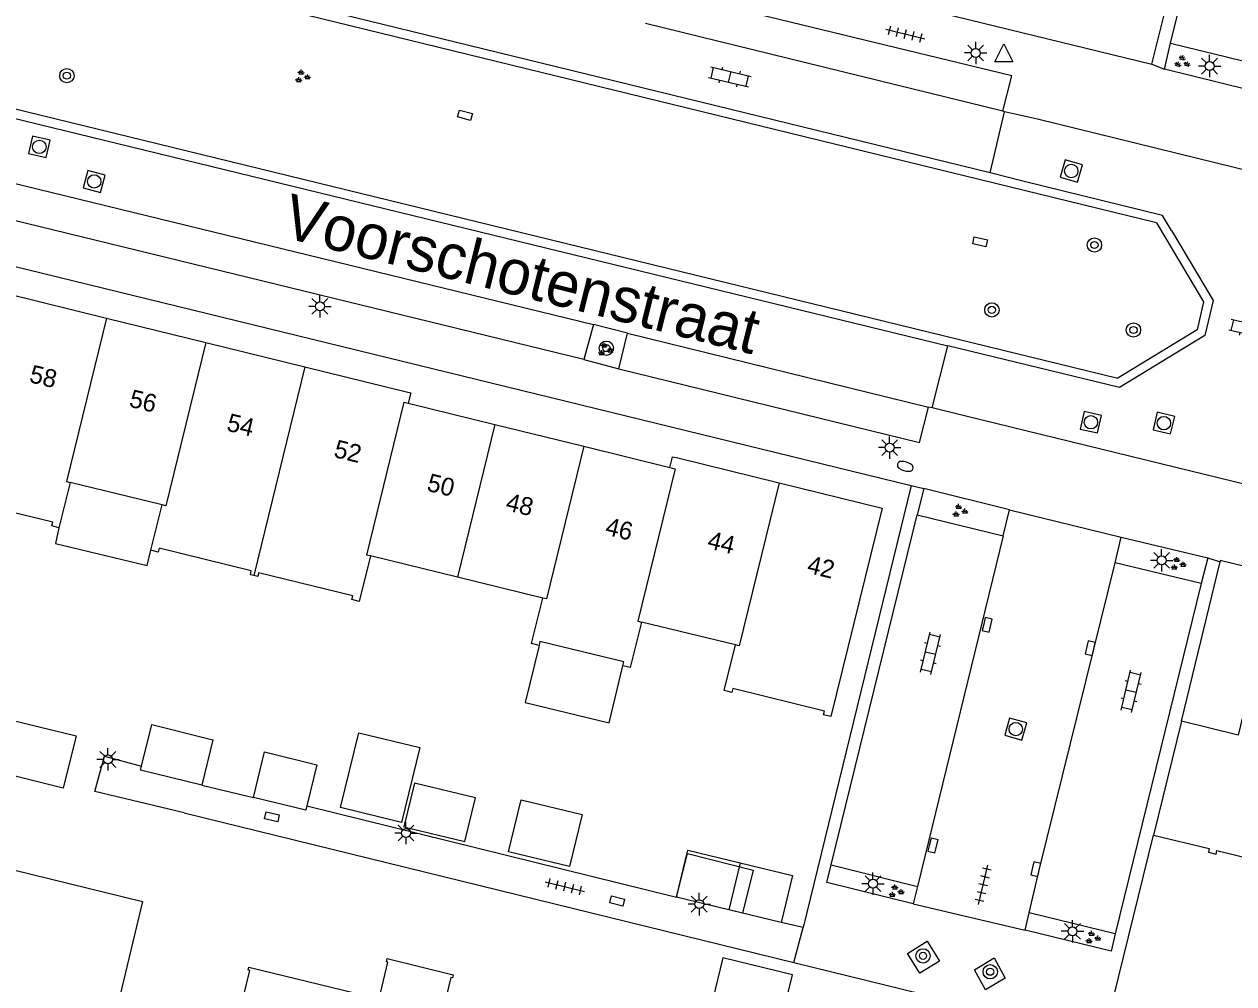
# Model space of a CAD drawing. Extents: x 125000 to 129004, y 397500 to 399008.
# Drawn here: x 126369.4 to 126436.9, y 398219.6 to 398273.2 of the extents above; entities that cross this region are included whole.
import ezdxf

# ---------------------------------------------------------------- set-up
doc = ezdxf.new("R2010")
doc.units = 0
for name, color, linetype in [('gg-afsc-erfafscheiding', 7, 'Continuous'), ('gg-afsc-hekwerk', 7, 'Continuous'), ('gg-afsc-muur', 7, 'Continuous'), ('gg-anno-huisnummerreeks BGT', 7, 'Continuous'), ('gg-anno-openbare ruimte label', 7, 'Continuous'), ('gg-bbg-bijgebouw', 7, 'Continuous'), ('gg-bbg-gedigitaliseerde bijgebouw', 7, 'Continuous'), ('gg-bbg-hoofdgebouw', 7, 'Continuous'), ('gg-bbg-luifel en loopbrug', 7, 'Continuous'), ('gg-bbg-tussenscheiding', 7, 'Continuous'), ('gg-knt-verharding', 7, 'Continuous'), ('gg-knt-verharding nz', 7, 'Continuous'), ('gt-bbg-plantopografie pand', 7, 'Continuous'), ('gt-grn-weggrens', 7, 'Continuous'), ('gt-symb-boom', 7, 'Continuous'), ('gt-symb-brandkraan', 7, 'Continuous'), ('gt-symb-groenvak', 7, 'Continuous'), ('gt-symb-klinker verharding', 7, 'Continuous'), ('gt-symb-kolk', 7, 'Continuous'), ('gt-symb-kolk center center', 7, 'Continuous'), ('gt-symb-lichtmast', 7, 'Continuous'), ('gt-symb-rioolschacht', 7, 'Continuous'), ('gt-symb-tegel verharding', 7, 'Continuous'), ('gt-symb-waterafsluiter', 7, 'Continuous')]:
    doc.layers.add(name, color=color, linetype=linetype)

# ---------------------------------------------------------------- blocks, each defined once
blk = doc.blocks.new('gt0-LMAST')
at = {"layer": 'gt-symb-lichtmast'}
for p, q in [((-0.182, 0.173), (-0.447, 0.438)), ((-0.005, 0.246), (-0.005, 0.621)), ((0.172, 0.173), (0.437, 0.438)), ((-0.255, -0.004), (-0.63, -0.004)), ((-0.182, -0.181), (-0.447, -0.446)), ((-0.005, -0.254), (-0.005, -0.629)), ((0.437, -0.446), (0.172, -0.181)), ((0.245, -0.004), (0.62, -0.004))]:
    blk.add_line(p, q, dxfattribs=at)
blk.add_circle((-0.005, -0.004), 0.25, dxfattribs=at)
blk = doc.blocks.new('gt0-GRVAK')
at = {"layer": 'gt-symb-groenvak'}
for p, q in [((-0.11, 0.189), (-0.228, 0.24)), ((-0.182, 0.153), (0.088, 0.153)), ((-0.091, 0.211), (-0.156, 0.322)), ((-0.047, 0.214), (-0.047, 0.393)), ((-0.004, 0.211), (0.061, 0.322)), ((0.015, 0.189), (0.133, 0.24)), ((0.262, -0.052), (0.197, 0.059)), ((0.305, -0.049), (0.305, 0.13)), ((0.349, -0.052), (0.414, 0.059)), ((-0.245, -0.228), (-0.363, -0.177)), ((-0.318, -0.264), (-0.047, -0.264)), ((-0.226, -0.206), (-0.291, -0.095)), ((-0.183, -0.203), (-0.183, -0.024)), ((-0.139, -0.206), (-0.074, -0.095)), ((-0.12, -0.228), (-0.002, -0.177)), ((0.243, -0.074), (0.125, -0.023)), ((0.17, -0.11), (0.441, -0.11)), ((0.368, -0.074), (0.486, -0.023))]:
    blk.add_line(p, q, dxfattribs=at)
blk = doc.blocks.new('gt0-WAFSL')
at = {"layer": 'gt-symb-waterafsluiter'}
for p, q in [((-0.5, -0.333), (0, 0.667)), ((0, 0.667), (0.5, -0.333)), ((0.5, -0.333), (-0.5, -0.333))]:
    blk.add_line(p, q, dxfattribs=at)
blk = doc.blocks.new('gt0-RS')
at = {"layer": 'gt-symb-rioolschacht'}
blk.add_lwpolyline([(-0.5, -0.5), (0.5, -0.5), (0.5, 0.5), (-0.5, 0.5)], close=True, dxfattribs=at)
blk.add_circle((0, 0), 0.375, dxfattribs=at)
blk = doc.blocks.new('gt0-BOOM')
at = {"layer": 'gt-symb-boom'}
for radius in [0.4, 0.2]:
    blk.add_circle((0, 0), radius, dxfattribs=at)
blk = doc.blocks.new('gt0-KL1')
at = {"layer": 'gt-symb-klinker verharding'}
for p, q in [((-1.15, 0.3), (1.15, 0.3)), ((-1, -0.3), (-1, 0.3)), ((-0.5, 0.3), (-0.5, 0.45)), ((0, -0.3), (0, 0.3)), ((0.5, 0.3), (0.5, 0.45)), ((1, -0.3), (1, 0.3)), ((-1.15, -0.3), (1.15, -0.3)), ((-0.5, -0.45), (-0.5, -0.3)), ((0.5, -0.45), (0.5, -0.3))]:
    blk.add_line(p, q, dxfattribs=at)
blk = doc.blocks.new('gt0-KOLKCC')
at = {"layer": 'gt-symb-kolk center center'}
blk.add_lwpolyline([(-0.375, 0.2), (0.375, 0.2), (0.375, -0.2), (-0.375, -0.2)], close=True, dxfattribs=at)
blk = doc.blocks.new('gt0-KOLK')
at = {"layer": 'gt-symb-kolk'}
blk.add_lwpolyline([(0, 0), (0.375, 0), (0.375, 0.4), (-0.375, 0.4), (-0.375, 0), (0, 0)], dxfattribs=at)
blk = doc.blocks.new('gt0-TEG1')
at = {"layer": 'gt-symb-tegel verharding'}
for p, q in [((-1.125, 0), (1.125, 0)), ((-0.9, -0.25), (-0.9, 0.25)), ((-0.45, -0.25), (-0.45, 0.25)), ((0, -0.25), (0, 0.25)), ((0.45, -0.25), (0.45, 0.25)), ((0.9, -0.25), (0.9, 0.25))]:
    blk.add_line(p, q, dxfattribs=at)
blk = doc.blocks.new('gt0-BR')
at = {"layer": 'gt-symb-brandkraan'}
for centre, radius, start, end in [((-0.244, 0), 0.206, 107.56694, 252.43307), ((0.599, -2.664), 3, 106.89205, 107.56694), ((0, -0.691), 0.938, 73.10799, 106.89205), ((-0.599, -2.664), 3, 72.43309, 73.10799), ((0.244, 0), 0.206, 287.56695, 72.43309), ((0.599, 2.664), 3, 252.43307, 253.10797), ((0, 0.691), 0.938, 253.10797, 286.89206), ((-0.599, 2.664), 3, 286.89206, 287.56695)]:
    blk.add_arc(centre, radius, start, end, dxfattribs=at)

msp = doc.modelspace()

# ---------------------------------------------------------------- linework, layer by layer
at = {"layer": 'gg-afsc-erfafscheiding'}
for p, q in [((126379.348, 398230.678), (126382.237, 398229.993)), ((126385.218, 398229.527), (126405.834, 398224.429))]:
    msp.add_line(p, q, dxfattribs=at)
msp.add_lwpolyline([(126373.387, 398230.333), (126373.917, 398232.305), (126375.989, 398231.752)], dxfattribs=at)
at = {"layer": 'gg-afsc-hekwerk'}
for p, q in [((126432.346, 398270.92), (126434.347, 398278.885)), ((126418.934, 398247.413), (126412.894, 398222.733)), ((126434.011, 398234.258), (126436.166, 398243.146)), ((126378.37, 398229.14), (126412.376, 398220.79)), ((126412.894, 398222.733), (126411.668, 398223.028))]:
    msp.add_line(p, q, dxfattribs=at)
msp.add_lwpolyline([(126412.376, 398220.79), (126429.666, 398216.545), (126432.45, 398227.902)], dxfattribs=at)
at = {"layer": 'gg-afsc-muur'}
msp.add_line((126378.37, 398229.14), (126373.387, 398230.333), dxfattribs=at)
at = {"layer": 'gg-bbg-bijgebouw'}
for points in [[(126375.989, 398231.752), (126376.559, 398234.064), (126379.976, 398233.221), (126379.348, 398230.678)], [(126382.237, 398229.993), (126382.86, 398232.541), (126385.778, 398231.828), (126385.218, 398229.527)], [(126379.348, 398230.678), (126375.932, 398231.522), (126375.989, 398231.752)], [(126385.218, 398229.527), (126385.158, 398229.282), (126382.237, 398229.993)]]:
    msp.add_lwpolyline(points, dxfattribs=at)
at = {"layer": 'gg-bbg-gedigitaliseerde bijgebouw'}
for p, q in [((126409.382, 398226.354), (126408.751, 398223.729)), ((126408.751, 398223.729), (126405.834, 398224.429))]:
    msp.add_line(p, q, dxfattribs=at)
for points in [[(126368.747, 398234.32), (126372.34, 398233.437), (126371.624, 398230.524), (126368.031, 398231.407), (126368.747, 398234.32)], [(126391.51, 398232.786), (126390.493, 398228.608), (126387.092, 398229.435), (126388.109, 398233.613), (126391.51, 398232.786)], [(126391.215, 398230.795), (126390.629, 398228.365), (126394.031, 398227.544), (126394.617, 398229.975), (126391.215, 398230.795)], [(126396.462, 398226.958), (126397.165, 398229.875), (126400.567, 398229.054), (126399.864, 398226.138), (126396.462, 398226.958)], [(126405.834, 398224.429), (126406.465, 398227.054), (126409.382, 398226.354)]]:
    msp.add_lwpolyline(points, dxfattribs=at)
at = {"layer": 'gg-bbg-hoofdgebouw'}
for p, q in [((126368.481, 398258.116), (126374.032, 398256.751)), ((126374.032, 398256.751), (126379.57, 398255.389)), ((126379.57, 398255.389), (126385.105, 398254.028)), ((126385.105, 398254.028), (126390.78, 398252.633)), ((126390.866, 398252.004), (126395.705, 398250.814)), ((126395.705, 398250.814), (126400.664, 398249.595)), ((126400.664, 398249.595), (126405.471, 398248.413)), ((126405.902, 398248.946), (126411.557, 398247.556)), ((126372.008, 398247.582), (126371.386, 398245.051)), ((126377.136, 398246.321), (126372.008, 398247.582)), ((126411.557, 398247.556), (126417.319, 398246.139)), ((126376.514, 398243.791), (126377.136, 398246.321)), ((126393.619, 398242.288), (126388.759, 398243.474)), ((126398.37, 398241.128), (126393.619, 398242.288)), ((126409.12, 398238.508), (126403.875, 398239.782)), ((126434.011, 398234.258), (126432.45, 398227.902))]:
    msp.add_line(p, q, dxfattribs=at)
for points in [[(126390.78, 398252.633), (126391.007, 398252.577), (126390.866, 398252.004)], [(126405.471, 398248.413), (126405.619, 398249.016), (126405.902, 398248.946)], [(126371.386, 398245.051), (126370.981, 398245.155), (126371.035, 398245.368), (126365.888, 398246.609), (126365.839, 398246.405), (126365.631, 398246.459)], [(126417.319, 398246.139), (126414.45, 398234.511), (126414.041, 398234.606), (126414.091, 398234.82), (126408.971, 398236.078), (126408.918, 398235.864), (126408.71, 398235.914)], [(126382.257, 398242.381), (126382.062, 398242.43), (126382.115, 398242.643), (126376.97, 398243.904), (126376.918, 398243.69), (126376.514, 398243.791)], [(126388.759, 398243.474), (126388.141, 398240.94), (126387.933, 398240.991)], [(126387.933, 398240.991), (126387.724, 398241.042), (126387.776, 398241.256), (126382.523, 398242.542), (126382.471, 398242.328), (126382.257, 398242.381)], [(126398.167, 398238.483), (126397.749, 398238.585), (126398.37, 398241.128)], [(126438.98, 398240.933), (126437.167, 398233.483), (126434.011, 398234.258)], [(126403.875, 398239.782), (126403.26, 398237.247), (126402.845, 398237.345)], [(126402.845, 398237.345), (126402.896, 398237.56), (126398.219, 398238.697), (126398.167, 398238.483)], [(126408.71, 398235.914), (126408.502, 398235.964), (126409.12, 398238.508)], [(126432.45, 398227.902), (126435.56, 398227.143), (126435.512, 398226.937), (126435.935, 398226.833), (126435.985, 398227.041), (126441.133, 398225.781), (126441.081, 398225.574), (126441.296, 398225.52)], [(126363.351, 398223.864), (126368.055, 398222.709), (126368.85, 398225.953), (126376.045, 398224.19), (126373.902, 398215.263), (126370.093, 398216.172), (126369.495, 398213.806), (126368.707, 398213.995), (126368.149, 398211.671), (126360.814, 398213.434)], [(126379.277, 398209.069), (126382.026, 398220.333), (126381.939, 398220.357), (126381.986, 398220.528), (126389.254, 398218.763), (126389.737, 398220.809), (126389.65, 398220.83), (126389.695, 398221.015), (126393.385, 398220.109), (126393.34, 398219.924), (126393.252, 398219.946), (126391.71, 398213.545)]]:
    msp.add_lwpolyline(points, dxfattribs=at)
at = {"layer": 'gg-bbg-luifel en loopbrug'}
msp.add_line((126411.668, 398223.028), (126408.751, 398223.729), dxfattribs=at)
for points in [[(126371.386, 398245.051), (126371.188, 398244.18), (126376.31, 398242.944), (126376.514, 398243.791)], [(126398.167, 398238.483), (126397.399, 398235.295), (126402.078, 398234.166), (126402.845, 398237.345)], [(126409.382, 398226.354), (126412.299, 398225.653), (126411.668, 398223.028)], [(126411.051, 398214.946), (126412.307, 398220.095), (126408.421, 398221.043), (126407.11, 398215.67)]]:
    msp.add_lwpolyline(points, dxfattribs=at)
at = {"layer": 'gg-bbg-tussenscheiding'}
for p, q in [((126385.105, 398254.028), (126382.257, 398242.381)), ((126395.705, 398250.814), (126393.619, 398242.288))]:
    msp.add_line(p, q, dxfattribs=at)
for points in [[(126374.032, 398256.751), (126371.802, 398247.633), (126372.008, 398247.582)], [(126379.57, 398255.389), (126377.34, 398246.271), (126377.136, 398246.321)], [(126388.759, 398243.474), (126388.553, 398243.524), (126390.64, 398252.06), (126390.866, 398252.004)], [(126400.664, 398249.595), (126398.58, 398241.077), (126398.37, 398241.128)], [(126405.471, 398248.413), (126405.755, 398248.343), (126403.673, 398239.831), (126403.875, 398239.782)], [(126411.557, 398247.556), (126409.332, 398238.457), (126409.12, 398238.508)]]:
    msp.add_lwpolyline(points, dxfattribs=at)
at = {"layer": 'gg-knt-verharding'}
for p, q in [((126333.839, 398295.002), (126432.346, 398270.92)), ((126433.403, 398272.088), (126438.669, 398293.39)), ((126328.44, 398278.308), (126430.454, 398253.401)), ((126329.473, 398277.528), (126420.97, 398255.202)), ((126433.053, 398270.635), (126433.403, 398272.088)), ((126433.403, 398272.088), (126438.194, 398270.92)), ((126400.663, 398254.432), (126335.48, 398270.359)), ((126437.802, 398269.467), (126433.053, 398270.635)), ((126327.675, 398269.71), (126418.934, 398247.413)), ((126423.334, 398264.85), (126424.139, 398268.27)), ((126424.139, 398268.27), (126424.036, 398268.3)), ((126425.164, 398264.383), (126423.334, 398264.85)), ((126401.204, 398256.387), (126400.663, 398254.432)), ((126403.108, 398255.911), (126401.204, 398256.387)), ((126402.618, 398253.912), (126403.108, 398255.911)), ((126420.108, 398251.75), (126420.97, 398255.202)), ((126400.663, 398254.432), (126402.618, 398253.912)), ((126420.108, 398251.75), (126419.9, 398251.773)), ((126419.634, 398247.232), (126419.257, 398245.769)), ((126424.409, 398246.056), (126419.634, 398247.232)), ((126424.053, 398244.6), (126424.409, 398246.056)), ((126414.464, 398226.236), (126419.257, 398245.769)), ((126419.257, 398245.769), (126424.053, 398244.6)), ((126424.053, 398244.6), (126419.276, 398225.035)), ((126430.31, 398243.093), (126430.644, 398244.534)), ((126430.644, 398244.534), (126435.486, 398243.363)), ((126435.113, 398241.948), (126430.31, 398243.093)), ((126435.486, 398243.363), (126435.113, 398241.948)), ((126435.113, 398241.948), (126430.316, 398222.383)), ((126414.464, 398226.236), (126419.276, 398225.035)), ((126419.276, 398225.035), (126419.041, 398224.065)), ((126425.282, 398222.589), (126425.508, 398223.559)), ((126430.316, 398222.383), (126425.508, 398223.559))]:
    msp.add_line(p, q, dxfattribs=at)
for points in [[(126432.617, 398262.065), (126336.086, 398285.673), (126329.906, 398287.175)], [(126423.334, 398264.85), (126336.206, 398286.158), (126331.881, 398287.232)], [(126424.036, 398268.3), (126424.546, 398270.278), (126404.573, 398275.128)], [(126453.519, 398261.075), (126425.974, 398267.855), (126424.139, 398268.27)], [(126433.456, 398261.633), (126432.953, 398262.473), (126425.164, 398264.383)], [(126432.617, 398262.065), (126435.244, 398257.654), (126434.875, 398256.095), (126430.454, 398253.401)], [(126433.456, 398261.633), (126435.777, 398257.736), (126435.314, 398255.777), (126430.542, 398252.869), (126420.97, 398255.202)], [(126402.618, 398253.912), (126419.395, 398249.811), (126419.9, 398251.773)], [(126449.701, 398244.529), (126447.843, 398244.953), (126421.979, 398251.27), (126420.108, 398251.75)], [(126425.508, 398223.559), (126426.076, 398225.949), (126429.11, 398238.276), (126430.31, 398243.093)], [(126483.908, 398231.619), (126436.172, 398243.227), (126436.166, 398243.146)], [(126419.041, 398224.065), (126414.226, 398225.258), (126414.464, 398226.236)], [(126430.316, 398222.383), (126430.077, 398221.423), (126425.282, 398222.589)], [(126418.714, 398221.298), (126419.811, 398221.97), (126420.503, 398220.867), (126419.406, 398220.194), (126418.714, 398221.298)], [(126422.457, 398220.385), (126423.549, 398221.046), (126424.166, 398219.917), (126423.074, 398219.256), (126422.457, 398220.385)]]:
    msp.add_lwpolyline(points, dxfattribs=at)
at = {"layer": 'gg-knt-verharding nz'}
for p, q in [((126424.036, 398268.3), (126404.114, 398273.191)), ((126335.947, 398272.314), (126401.204, 398256.387)), ((126403.108, 398255.911), (126419.9, 398251.773))]:
    msp.add_line(p, q, dxfattribs=at)
at = {"layer": 'gt-bbg-plantopografie pand'}
msp.add_lwpolyline([(126405.834, 398224.429), (126406.453, 398226.873), (126410.121, 398225.945), (126409.513, 398223.546), (126405.834, 398224.429)], dxfattribs=at)
at = {"layer": 'gt-grn-weggrens'}
for p, q in [((126432.346, 398270.92), (126433.053, 398270.635)), ((126418.934, 398247.413), (126419.634, 398247.232)), ((126424.409, 398246.056), (126430.644, 398244.534)), ((126435.486, 398243.363), (126436.166, 398243.146)), ((126419.041, 398224.065), (126425.282, 398222.589)), ((126412.376, 398220.79), (126412.894, 398222.733))]:
    msp.add_line(p, q, dxfattribs=at)

# ---------------------------------------------------------------- block references
at = {"layer": 'gt-symb-boom'}
for p in [(126371.825, 398270.279), (126429.152, 398260.83), (126423.429, 398257.208), (126431.331, 398256.086), (126401.924, 398255.07), (126419.588, 398221.16), (126423.336, 398220.273)]:
    msp.add_blockref('gt0-BOOM', p, dxfattribs=at)
at = {"layer": 'gt-symb-brandkraan', "rotation": -16.73216022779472}
msp.add_blockref('gt0-BR', (126418.598, 398248.476), dxfattribs=at)
at = {"layer": 'gt-symb-groenvak', "rotation": -15.7172524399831}
msp.add_blockref('gt0-GRVAK', (126434.032, 398271.031), dxfattribs=at)
at = {"layer": 'gt-symb-groenvak'}
for p in [(126384.946, 398270.224), (126401.848, 398254.986), (126421.623, 398245.987), (126433.795, 398243.025), (126418.064, 398224.754), (126429.041, 398222.166)]:
    msp.add_blockref('gt0-GRVAK', p, dxfattribs=at)
at = {"layer": 'gt-symb-klinker verharding'}
for p, rotation in [((126408.81, 398270.211), -13.174926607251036), ((126437.831, 398256.13), -13.174926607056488), ((126420.004, 398238.044), 76.58892815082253), ((126431.197, 398235.923), 76.58892815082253)]:
    msp.add_blockref('gt0-KL1', p, dxfattribs=dict(at, rotation=rotation))
at = {"layer": 'gt-symb-kolk'}
for p, rotation in [((126422.974, 398239.676), -102.35482691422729), ((126429.11, 398238.276), 76.1722049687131), ((126419.951, 398227.368), -103.82779503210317), ((126426.076, 398225.949), 76.64465903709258)]:
    msp.add_blockref('gt0-KOLK', p, dxfattribs=dict(at, rotation=rotation))
at = {"layer": 'gt-symb-kolk center center'}
for p, rotation in [((126394.034, 398268.073), 165.35262473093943), ((126422.772, 398261.012), 167.3531465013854), ((126383.265, 398228.926), -12.827123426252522), ((126402.531, 398224.218), -14.119602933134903)]:
    msp.add_blockref('gt0-KOLKCC', p, dxfattribs=dict(at, rotation=rotation))
at = {"layer": 'gt-symb-lichtmast'}
for p in [(126422.533, 398271.55), (126435.58, 398270.818), (126385.946, 398257.41), (126417.73, 398249.528), (126432.905, 398243.236), (126374.119, 398232.125), (126390.748, 398228.017), (126416.801, 398225.188), (126407.11, 398224.049), (126427.932, 398222.535)]:
    msp.add_blockref('gt0-LMAST', p, dxfattribs=at)
at = {"layer": 'gt-symb-rioolschacht'}
for p, rotation in [((126370.292, 398266.305), 167.11702052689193), ((126427.86, 398264.959), 73.73979529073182), ((126373.35, 398264.375), 165.64421500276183), ((126428.953, 398250.937), -12.771242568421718), ((126433.026, 398250.888), 166.40843956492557), ((126424.764, 398233.814), 74.28274755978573)]:
    msp.add_blockref('gt0-RS', p, dxfattribs=dict(at, rotation=rotation))
at = {"layer": 'gt-symb-tegel verharding'}
for p, rotation in [((126418.603, 398272.605), -13.702889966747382), ((126422.948, 398225.122), 76.75619797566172), ((126399.609, 398225.023), -13.772145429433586)]:
    msp.add_blockref('gt0-TEG1', p, dxfattribs=dict(at, rotation=rotation))
at = {"layer": 'gt-symb-waterafsluiter'}
msp.add_blockref('gt0-WAFSL', (126424.097, 398271.385), dxfattribs=at)

# ---------------------------------------------------------------- texts
at = {"layer": 'gg-anno-huisnummerreeks BGT'}
for s, p in [('58', (126369.676, 398253.187)), ('56', (126375.245, 398251.817)), ('54', (126380.682, 398250.48)), ('52', (126386.665, 398249.009)), ('50', (126391.858, 398247.125)), ('48', (126396.259, 398246.043)), ('46', (126401.807, 398244.679)), ('44', (126407.503, 398243.917)), ('42', (126413.065, 398242.55))]:
    msp.add_text(s, height=1, rotation=346.2, dxfattribs=at).set_placement(p)
at = {"layer": 'gg-anno-openbare ruimte label'}
msp.add_text('Voorschotenstraat', height=2.5, rotation=346, dxfattribs=at).set_placement((126383.745, 398261.291))

doc.saveas('drawing.dxf')
